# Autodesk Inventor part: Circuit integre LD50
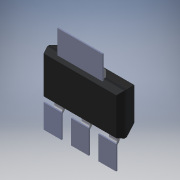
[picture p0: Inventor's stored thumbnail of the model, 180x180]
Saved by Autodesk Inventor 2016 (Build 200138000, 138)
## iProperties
Created: 2018-03
Part Number: Circuit integre LD50
Material: Générique
Document SubType Name: Modeling
Designer: Bruno
Density: 1 g/cm^3
Appearance: Par défaut
Author: Bruno
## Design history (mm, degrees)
feature "Composite1"
body "Srf1"
